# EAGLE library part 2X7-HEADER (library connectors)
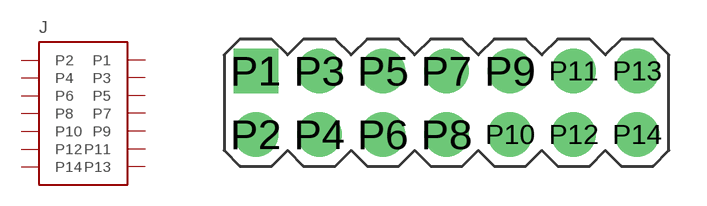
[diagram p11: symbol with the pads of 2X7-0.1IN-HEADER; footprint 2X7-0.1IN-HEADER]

Designator prefix J

## 2X7-HEADER0.1IN  [2X7-0.1IN-HEADER]
P1  P1  pas
P2  P2  pas
P3  P3  pas
P4  P4  pas
P5  P5  pas
P6  P6  pas
P7  P7  pas
P8  P8  pas
P9  P9  pas
P10  P10  pas
P11  P11  pas
P12  P12  pas
P13  P13  pas
P14  P14  pas

## Footprint 2X7-0.1IN-HEADER (pad centres in mm)
drill 1.05 pad 1.778 square: P1 -7.62,1.27
drill 1.05 pad 1.778 round: P2 -7.62,-1.27; P3 -5.08,1.27; P4 -5.08,-1.27; P5 -2.54,1.27; P6 -2.54,-1.27; P7 0,1.27; P8 0,-1.27; P9 2.54,1.27; P10 2.54,-1.27; P11 5.08,1.27; P12 5.08,-1.27; P13 7.62,1.27; P14 7.62,-1.27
